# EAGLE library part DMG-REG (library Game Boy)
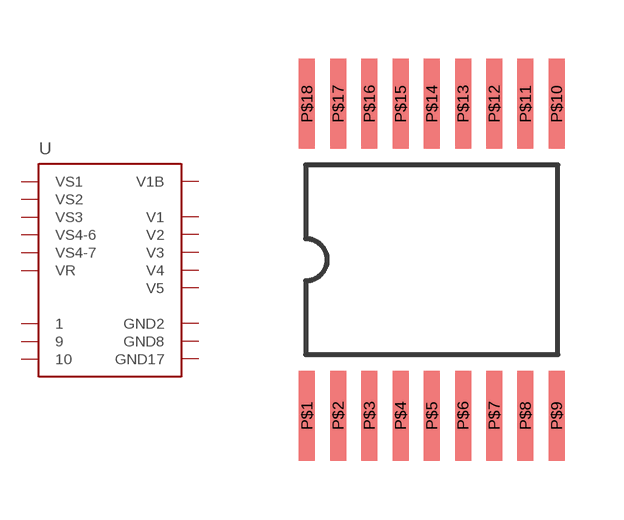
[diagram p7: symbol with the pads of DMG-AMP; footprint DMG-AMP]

Designator prefix -

## DMG-REG  [DMG-AMP]
P$1  1
P$2  GND2
P$3  VS1
P$4  VS2
P$5  VS3
P$6  VS4-6
P$7  VS4-7
P$8  GND8
P$9  9
P$10  10
P$11  V1B
P$12  V1
P$13  V4
P$14  V5
P$15  V2
P$16  V3
P$17  GND17
P$18  VR

## Footprint DMG-AMP (pad centres in mm)
smd 0.406 x 2.286: P$1 -3.175,-3.969; P$2 -2.381,-3.969; P$3 -1.587,-3.969; P$4 -0.794,-3.969; P$5 0,-3.969; P$6 0.794,-3.969; P$7 1.587,-3.969; P$8 2.381,-3.969; P$9 3.175,-3.969; P$10 3.175,3.969; P$11 2.381,3.969; P$12 1.587,3.969; P$13 0.794,3.969; P$14 0,3.969; P$15 -0.794,3.969; P$16 -1.587,3.969; P$17 -2.381,3.969; P$18 -3.175,3.969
